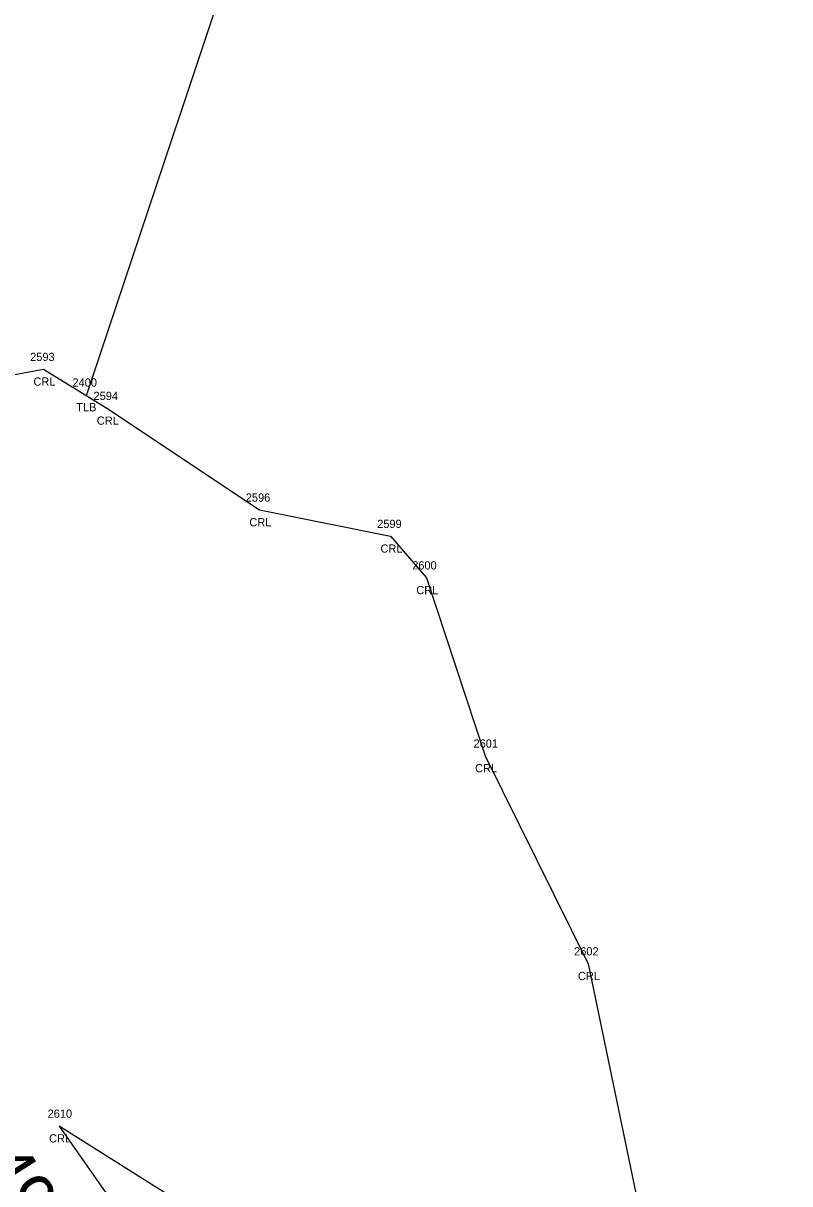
# Model space of a CAD drawing. Extents: x 2266664 to 2272542, y 716533 to 724777.
# Drawn here: x 2271174.6 to 2271267.8, y 722810 to 722951 of the extents above; entities that cross this region are included whole.
import ezdxf

# ---------------------------------------------------------------- set-up
doc = ezdxf.new("R2010")
doc.units = 0
for name, color, linetype in [('RD_EX_H2O', 7, 'Continuous'), ('RD_EX_H2O_txCode', 7, 'Continuous'), ('RD_EX_VEG', 7, 'Continuous'), ('RD_EX_VEG_txCode', 7, 'Continuous'), ('RD_HC_Data', 7, 'Continuous'), ('RD_SMD_Locator', 7, 'Continuous')]:
    doc.layers.add(name, color=color, linetype=linetype)

msp = doc.modelspace()

# ---------------------------------------------------------------- linework, layer by layer
at = {"layer": 'RD_EX_H2O'}
msp.add_lwpolyline([(2271133.84, 722916.93), (2271154.62, 722904.78), (2271177.12, 722908.95), (2271184.82, 722904.21), (2271203.34, 722891.87), (2271219.27, 722888.67), (2271223.62, 722883.63), (2271230.75, 722861.99), (2271243.25, 722836.75), (2271251.03, 722799.32), (2271257.08, 722776.2), (2271255.58, 722768.16), (2271246.13, 722767.9), (2271238.78, 722774.24), (2271234.51, 722782.33), (2271223.85, 722788.75), (2271179.02, 722817.03), (2271186.37, 722806.5), (2271219.28, 722770.37), (2271265.72, 722734.75), (2271320.84, 722716.15)], dxfattribs=at)
at = {"layer": 'RD_EX_VEG'}
msp.add_lwpolyline([(2271459.81, 723324.47), (2271430.14, 723343.39), (2271397.55, 723294.31), (2271226.14, 723037.24), (2271182.34, 722905.84)], dxfattribs=at)
at = {"layer": 'RD_SMD_Locator'}
for centre in [(2271177.12, 722908.95), (2271182.34, 722905.84), (2271184.82, 722904.21), (2271203.34, 722891.87), (2271219.27, 722888.67), (2271223.62, 722883.63), (2271230.75, 722861.99), (2271243.25, 722836.75), (2271179.02, 722817.03)]:
    msp.add_circle(centre, 0.001, dxfattribs=at)

# ---------------------------------------------------------------- texts
at = {"layer": 'RD_EX_H2O_txCode'}
for s, p in [('2593', (2271175.49, 722909.95)), ('CRL', (2271175.89, 722906.95)), ('2594', (2271183.19, 722905.21)), ('CRL', (2271183.59, 722902.21)), ('2596', (2271201.68, 722892.87)), ('CRL', (2271202.11, 722889.87)), ('2599', (2271217.64, 722889.67)), ('CRL', (2271218.04, 722886.67)), ('2600', (2271221.89, 722884.63)), ('CRL', (2271222.39, 722881.63)), ('2601', (2271229.34, 722862.99)), ('CRL', (2271229.53, 722859.99)), ('2602', (2271241.56, 722837.75)), ('CRL', (2271242.02, 722834.75)), ('2610', (2271177.61, 722818.03)), ('CRL', (2271177.79, 722815.03))]:
    msp.add_text(s, height=1, dxfattribs=at).set_placement(p)
at = {"layer": 'RD_EX_VEG_txCode'}
for s, p in [('2400', (2271180.63, 722906.84)), ('TLB', (2271181.09, 722903.84))]:
    msp.add_text(s, height=1, dxfattribs=at).set_placement(p)
at = {"layer": 'RD_HC_Data'}
msp.add_text('S 32%%d 26\' 49" E', height=6, rotation=302.4469, dxfattribs=at).set_placement((2271150.72, 722841.66))

doc.saveas('drawing.dxf')
